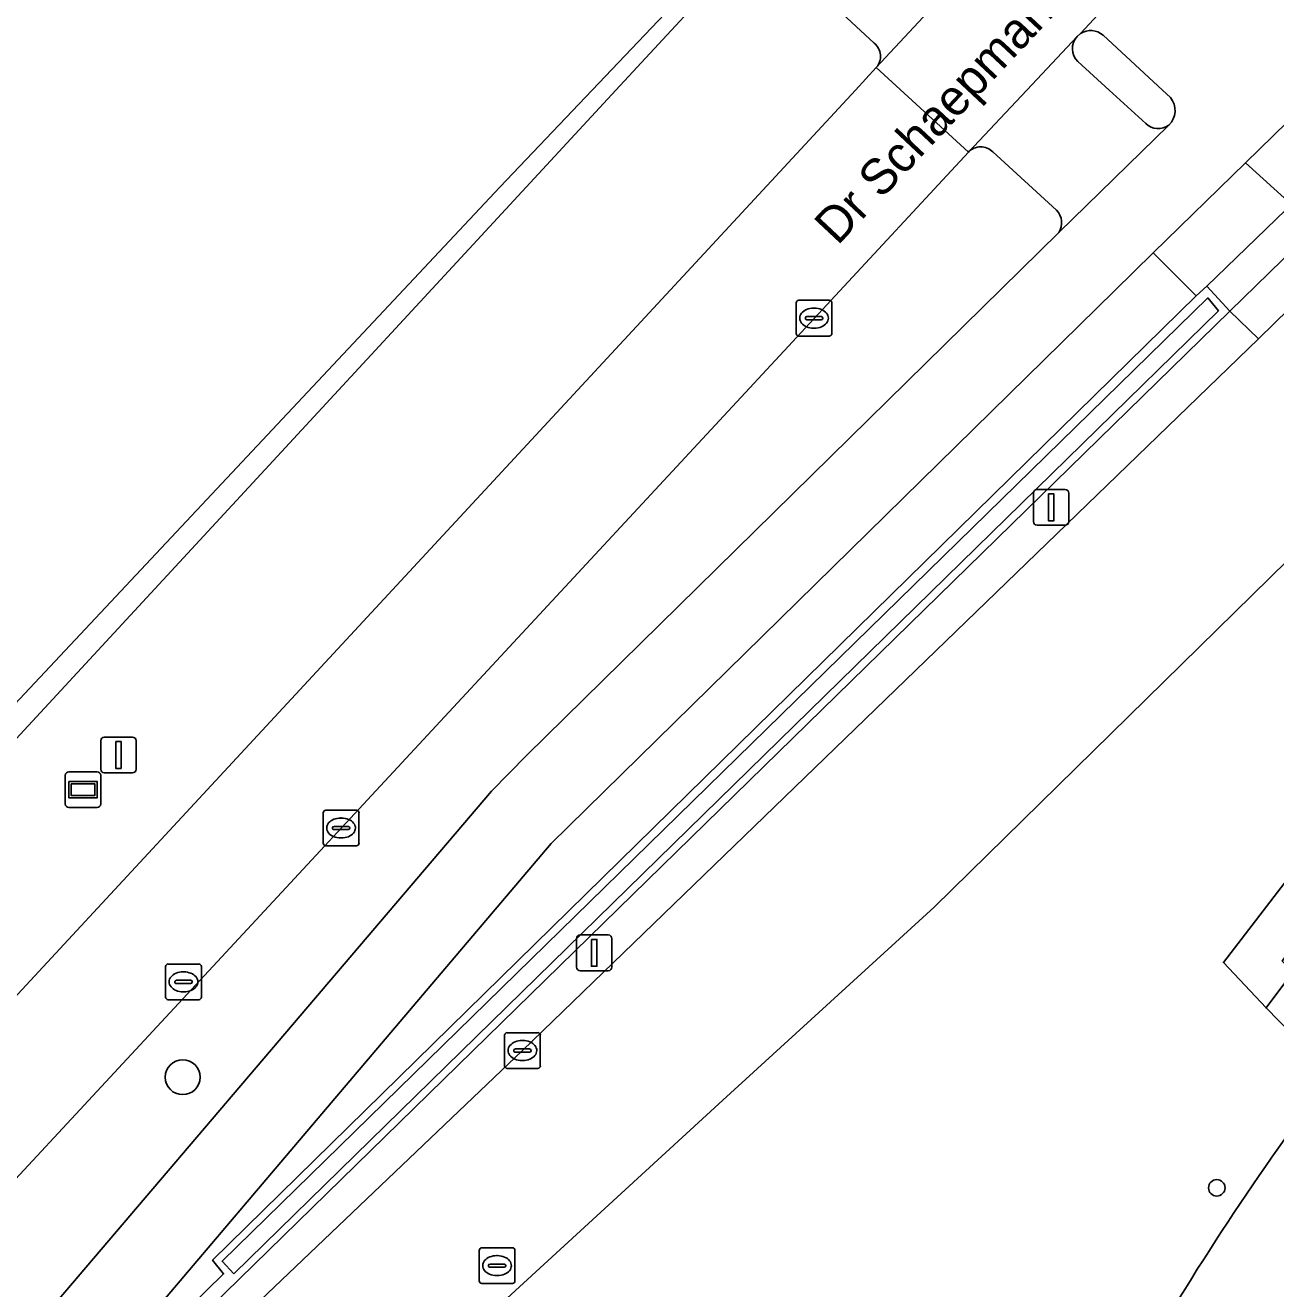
# Model space of a CAD drawing. Extents: x 161402 to 161933, y 381647 to 382315.
# Drawn here: x 161714.34 to 161749.33, y 382216.45 to 382251.82 of the extents above; entities that cross this region are included whole.
import ezdxf

# ---------------------------------------------------------------- set-up
doc = ezdxf.new("R2010")
doc.units = 0
for name, color, linetype in [('IMGEO_Berm_groen', 7, 'Continuous'), ('IMGEO_Boom', 7, 'Continuous'), ('IMGEO_Fietspad_open', 7, 'Continuous'), ('IMGEO_Groenvoorziening', 7, 'Continuous'), ('IMGEO_Kolk', 7, 'Continuous'), ('IMGEO_Lichtmast', 7, 'Continuous'), ('IMGEO_Muur', 7, 'Continuous'), ('IMGEO_Openbare_ruimte_label', 7, 'Continuous'), ('IMGEO_Pand', 7, 'Continuous'), ('IMGEO_Rijbaan_lokaal_gesloten', 7, 'Continuous'), ('IMGEO_Rijbaan_lokaal_open', 7, 'Continuous'), ('IMGEO_Rioolput', 7, 'Continuous'), ('IMGEO_Verkeerseiland_open', 7, 'Continuous'), ('IMGEO_Voetpad_gesloten', 7, 'Continuous'), ('IMGEO_Voetpad_open', 7, 'Continuous'), ('IMGEO_Wegwijzer', 7, 'Continuous')]:
    doc.layers.add(name, color=color, linetype=linetype)

msp = doc.modelspace()

# ---------------------------------------------------------------- linework, layer by layer
at = {"layer": 'IMGEO_Berm_groen'}
for points in [[(161765.113, 382264.207), (161748.486, 382247.967), (161749.768, 382246.799), (161766.553, 382263.178), (161766.895, 382262.953), (161769.85, 382265.834), (161770.184, 382265.542), (161755.779, 382251.492), (161750.251, 382245.958), (161751.001, 382245.149), (161766.659, 382260.549)], [(161734.565, 382254.001), (161730.864, 382250), (161697.412, 382213.802)], [(161738.093, 382251.314), (161735.183, 382254.02)], [(161737.568, 382250), (161738.153, 382250.632)], [(161701.048, 382210.574), (161737.568, 382250)], [(161740.731, 382248.263), (161709.017, 382214.078)], [(161743.193, 382246.637), (161741.415, 382248.269)], [(161727.383, 382230.373), (161728.369, 382231.371), (161743.258, 382246.014)], [(161747.1, 382244.24), (161745.906, 382245.446), (161744.819, 382244.379), (161729.058, 382228.913), (161711.467, 382208.182)], [(161711.914, 382207.765), (161713.169, 382208.748), (161728.253, 382223.117), (161748.845, 382243.038), (161748.046, 382243.815), (161715.85, 382212.342), (161715.57, 382212.632), (161719.892, 382216.863), (161719.584, 382217.248), (161747.1, 382244.24)], [(161709.873, 382209.811), (161727.383, 382230.373)]]:
    msp.add_lwpolyline(points, dxfattribs=at)
for centre, radius, start, end in [((161737.801, 382250.945), 0.471, 318.3858, 51.6697), ((161741.076, 382247.935), 0.476, 44.5516, 136.4535), ((161742.855, 382246.287), 0.487, 325.9277, 45.985)]:
    msp.add_arc(centre, radius, start, end, dxfattribs=at)
at = {"layer": 'IMGEO_Boom'}
msp.add_circle((161718.747, 382222.371), 0.489, dxfattribs=at)
at = {"layer": 'IMGEO_Fietspad_open'}
for points in [[(161689.262, 382184.152), (161697.545, 382192.886), (161698.197, 382193.597), (161711.467, 382208.182), (161729.058, 382228.913), (161744.819, 382244.379), (161745.906, 382245.446), (161748.486, 382247.967), (161765.113, 382264.207)], [(161746.097, 382253.988), (161743.866, 382251.581)], [(161744.502, 382251.534), (161746.159, 382250), (161746.382, 382249.794)], [(161746.337, 382249.017), (161743.258, 382246.014), (161728.369, 382231.371), (161727.383, 382230.373), (161709.873, 382209.811), (161695.051, 382193.536), (161687.761, 382185.921)]]:
    msp.add_lwpolyline(points, dxfattribs=at)
for centre, radius, start, end in [((161744.154, 382251.15), 0.518, 47.7745, 123.7726), ((161745.956, 382249.429), 0.561, 312.7967, 40.5741)]:
    msp.add_arc(centre, radius, start, end, dxfattribs=at)
at = {"layer": 'IMGEO_Groenvoorziening'}
msp.add_lwpolyline([(161720.173, 382216.864), (161747.726, 382243.82), (161747.429, 382244.182), (161719.85, 382217.217)], close=True, dxfattribs=at)
at = {"layer": 'IMGEO_Kolk'}
for p, q in [((161735.911, 382243.191), (161735.911, 382244.043)), ((161735.986, 382244.117), (161736.838, 382244.117)), ((161736.912, 382244.043), (161736.912, 382243.191)), ((161736.399, 382243.897), (161736.424, 382243.897)), ((161736.17, 382243.611), (161736.17, 382243.623)), ((161736.608, 382243.574), (161736.21, 382243.574)), ((161736.213, 382243.66), (161736.611, 382243.66)), ((161736.422, 382243.337), (161736.397, 382243.337)), ((161736.654, 382243.623), (161736.654, 382243.611)), ((161736.838, 382243.117), (161735.986, 382243.117)), ((161722.678, 382228.92), (161722.678, 382229.772)), ((161722.753, 382229.846), (161723.605, 382229.846)), ((161723.166, 382229.626), (161723.191, 382229.626)), ((161723.679, 382229.772), (161723.679, 382228.92)), ((161722.937, 382229.34), (161722.937, 382229.352)), ((161723.375, 382229.303), (161722.977, 382229.303)), ((161722.98, 382229.389), (161723.378, 382229.389)), ((161723.421, 382229.352), (161723.421, 382229.34)), ((161723.605, 382228.846), (161722.753, 382228.846)), ((161723.189, 382229.066), (161723.164, 382229.066)), ((161727.752, 382222.691), (161727.752, 382223.543)), ((161727.827, 382223.617), (161728.679, 382223.617)), ((161728.753, 382223.543), (161728.753, 382222.691)), ((161728.24, 382223.397), (161728.265, 382223.397)), ((161728.011, 382223.111), (161728.011, 382223.123)), ((161728.449, 382223.074), (161728.051, 382223.074)), ((161728.054, 382223.16), (161728.452, 382223.16)), ((161728.263, 382222.837), (161728.238, 382222.837)), ((161728.495, 382223.123), (161728.495, 382223.111)), ((161728.679, 382222.617), (161727.827, 382222.617))]:
    msp.add_line(p, q, dxfattribs=at)
for points in [[(161735.911, 382243.191), (161735.911, 382244.043)], [(161735.986, 382244.117), (161736.838, 382244.117)], [(161736.912, 382244.043), (161736.912, 382243.191)], [(161736.838, 382243.117), (161735.986, 382243.117)], [(161722.678, 382228.92), (161722.678, 382229.772)], [(161722.753, 382229.846), (161723.605, 382229.846)], [(161723.679, 382229.772), (161723.679, 382228.92)], [(161723.605, 382228.846), (161722.753, 382228.846)], [(161727.752, 382222.691), (161727.752, 382223.543)], [(161727.827, 382223.617), (161728.679, 382223.617)], [(161728.753, 382223.543), (161728.753, 382222.691)], [(161728.679, 382222.617), (161727.827, 382222.617)]]:
    msp.add_lwpolyline(points, dxfattribs=at)
for centre, radius, start, end in [((161735.988, 382244.041), 0.0765, 91.552, 178.448), ((161735.988, 382244.041), 0.0765, 91.552, 178.448), ((161736.836, 382244.041), 0.0765, 1.552, 88.448), ((161736.836, 382244.041), 0.0765, 1.552, 88.448), ((161736.21, 382243.62), 0.0403, 85.8775, 175.7526), ((161736.207, 382243.61), 0.0366, 178.938, 274.7102), ((161736.611, 382243.617), 0.043, 264.8664, 352.4533), ((161736.615, 382243.622), 0.0386, 1.7309, 96.639), ((161735.988, 382243.193), 0.0765, 181.552, 268.448), ((161735.988, 382243.193), 0.0765, 181.552, 268.448), ((161736.836, 382243.193), 0.0765, 271.552, 358.448), ((161736.836, 382243.193), 0.0765, 271.552, 358.448), ((161722.755, 382229.77), 0.0765, 91.552, 178.448), ((161722.755, 382229.77), 0.0765, 91.552, 178.448), ((161723.603, 382229.77), 0.0765, 1.552, 88.448), ((161723.603, 382229.77), 0.0765, 1.552, 88.448), ((161722.977, 382229.349), 0.0403, 85.8775, 175.7526), ((161722.974, 382229.339), 0.0366, 178.938, 274.7102), ((161723.378, 382229.346), 0.043, 264.8664, 352.4533), ((161723.382, 382229.351), 0.0386, 1.7309, 96.639), ((161722.755, 382228.922), 0.0765, 181.552, 268.448), ((161722.755, 382228.922), 0.0765, 181.552, 268.448), ((161723.603, 382228.922), 0.0765, 271.552, 358.448), ((161723.603, 382228.922), 0.0765, 271.552, 358.448), ((161727.829, 382223.541), 0.0765, 91.552, 178.448), ((161727.829, 382223.541), 0.0765, 91.552, 178.448), ((161728.677, 382223.541), 0.0765, 1.552, 88.448), ((161728.677, 382223.541), 0.0765, 1.552, 88.448), ((161728.051, 382223.12), 0.0403, 85.8775, 175.7526), ((161728.048, 382223.11), 0.0366, 178.938, 274.7102), ((161728.452, 382223.117), 0.043, 264.8664, 352.4533), ((161728.456, 382223.122), 0.0386, 1.7309, 96.639), ((161727.829, 382222.693), 0.0765, 181.552, 268.448), ((161727.829, 382222.693), 0.0765, 181.552, 268.448), ((161728.677, 382222.693), 0.0765, 271.552, 358.448), ((161728.677, 382222.693), 0.0765, 271.552, 358.448)]:
    msp.add_arc(centre, radius, start, end, dxfattribs=at)
for centre, major_axis, ratio, start_param, end_param in [((161736.398, 382243.617), (-0.387, 0.002), 0.722429, 4.712389, 7.853982), ((161736.423, 382243.617), (-0.39, 0.002), 0.717154, 1.570796, 4.712389), ((161723.165, 382229.346), (-0.387, 0.002), 0.722429, 4.712389, 7.853982), ((161723.19, 382229.346), (-0.39, 0.002), 0.717154, 1.570796, 4.712389), ((161728.239, 382223.117), (-0.387, 0.002), 0.722429, 4.712389, 7.853982), ((161728.264, 382223.117), (-0.39, 0.002), 0.717154, 1.570796, 4.712389)]:
    msp.add_ellipse(centre, major_axis=major_axis, ratio=ratio, start_param=start_param, end_param=end_param, dxfattribs=at)
at = {"layer": 'IMGEO_Lichtmast'}
for p, q in [((161742.652, 382238.821), (161743.442, 382238.821)), ((161743.442, 382238.821), (161742.652, 382238.821)), ((161742.552, 382237.921), (161742.552, 382238.721)), ((161742.552, 382238.721), (161742.552, 382237.921)), ((161743.542, 382238.721), (161743.542, 382237.921)), ((161743.542, 382237.921), (161743.542, 382238.721)), ((161743.442, 382237.821), (161742.652, 382237.821)), ((161742.652, 382237.821), (161743.442, 382237.821)), ((161716.453, 382230.989), (161716.453, 382231.789)), ((161716.453, 382231.789), (161716.453, 382230.989)), ((161716.553, 382231.889), (161717.343, 382231.889)), ((161717.343, 382231.889), (161716.553, 382231.889)), ((161717.443, 382231.789), (161717.443, 382230.989)), ((161717.443, 382230.989), (161717.443, 382231.789)), ((161717.343, 382230.889), (161716.553, 382230.889)), ((161716.553, 382230.889), (161717.343, 382230.889)), ((161729.765, 382225.452), (161729.765, 382226.252)), ((161729.765, 382226.252), (161729.765, 382225.452)), ((161729.865, 382226.352), (161730.655, 382226.352)), ((161730.655, 382226.352), (161729.865, 382226.352)), ((161730.755, 382226.252), (161730.755, 382225.452)), ((161730.755, 382225.452), (161730.755, 382226.252)), ((161730.655, 382225.352), (161729.865, 382225.352)), ((161729.865, 382225.352), (161730.655, 382225.352))]:
    msp.add_line(p, q, dxfattribs=at)
for points in [[(161742.972, 382238.696), (161743.122, 382238.696), (161743.122, 382237.946), (161742.972, 382237.946), (161742.972, 382238.696)], [(161716.873, 382231.764), (161717.023, 382231.764), (161717.023, 382231.014), (161716.873, 382231.014), (161716.873, 382231.764)], [(161730.185, 382226.227), (161730.335, 382226.227), (161730.335, 382225.477), (161730.185, 382225.477), (161730.185, 382226.227)]]:
    msp.add_lwpolyline(points, dxfattribs=at)
for centre, start, end in [((161742.652, 382238.721), 90, 180), ((161742.652, 382238.721), 90, 180), ((161743.442, 382238.721), 0, 90), ((161743.442, 382238.721), 360, 90), ((161742.652, 382237.921), 180, 270), ((161742.652, 382237.921), 180, 270), ((161743.442, 382237.921), 270, 0), ((161743.442, 382237.921), 270, 0), ((161716.553, 382231.789), 90, 180), ((161716.553, 382231.789), 90, 180), ((161717.343, 382231.789), 0, 90), ((161717.343, 382231.789), 360, 90), ((161716.553, 382230.989), 180, 270), ((161716.553, 382230.989), 180, 270), ((161717.343, 382230.989), 270, 0), ((161717.343, 382230.989), 270, 0), ((161729.865, 382226.252), 90, 180), ((161729.865, 382226.252), 90, 180), ((161730.655, 382226.252), 0, 90), ((161730.655, 382226.252), 360, 90), ((161729.865, 382225.452), 180, 270), ((161729.865, 382225.452), 180, 270), ((161730.655, 382225.452), 270, 0), ((161730.655, 382225.452), 270, 0)]:
    msp.add_arc(centre, 0.1, start, end, dxfattribs=at)
at = {"layer": 'IMGEO_Muur'}
for points in [[(161747.399, 382244.517), (161747.1, 382244.24), (161719.584, 382217.248), (161719.892, 382216.863), (161715.57, 382212.632), (161715.85, 382212.342), (161748.046, 382243.815)], [(161720.173, 382216.864), (161719.85, 382217.217), (161747.429, 382244.182), (161747.726, 382243.82)]]:
    msp.add_lwpolyline(points, close=True, dxfattribs=at)
at = {"layer": 'IMGEO_Pand'}
for centre, radius, start, end in [((161816.968, 382172.845), 82.616, 143.12172, 150.09585), ((161747.682, 382219.274), 0.23, 90, 270), ((161747.682, 382219.274), 0.23, 270, 90)]:
    msp.add_arc(centre, radius, start, end, dxfattribs=at)
at = {"layer": 'IMGEO_Rijbaan_lokaal_gesloten'}
for points in [[(161747.864, 382261.109), (161743.521, 382256.439), (161743.425, 382256.334), (161741.178, 382253.892), (161738.153, 382250.632), (161740.731, 382248.263), (161742.363, 382250), (161743.776, 382251.504), (161743.866, 382251.581), (161746.097, 382253.988), (161749.055, 382257.09)], [(161697.412, 382213.802), (161730.864, 382250), (161734.565, 382254.001), (161734.265, 382254.268), (161727.62, 382247.284), (161706.254, 382224.51), (161675.772, 382191.906)], [(161709.017, 382214.078), (161740.731, 382248.263), (161738.153, 382250.632), (161737.568, 382250), (161701.048, 382210.574), (161693.624, 382202.616), (161684.055, 382192.367), (161681.452, 382189.793)]]:
    msp.add_lwpolyline(points, dxfattribs=at)
at = {"layer": 'IMGEO_Rijbaan_lokaal_open'}
for points in [[(161766.659, 382260.549), (161751.001, 382245.149), (161748.845, 382243.038), (161728.253, 382223.117), (161713.169, 382208.748), (161711.914, 382207.765)], [(161710.972, 382200.713), (161733.859, 382221.725), (161739.772, 382227.133), (161755.602, 382242.666)]]:
    msp.add_lwpolyline(points, dxfattribs=at)
at = {"layer": 'IMGEO_Rioolput'}
for p, q in [((161718.268, 382224.613), (161718.268, 382225.465)), ((161718.343, 382225.539), (161719.195, 382225.539)), ((161718.756, 382225.319), (161718.781, 382225.319)), ((161719.269, 382225.465), (161719.269, 382224.613)), ((161718.527, 382225.033), (161718.527, 382225.045)), ((161718.965, 382224.996), (161718.567, 382224.996)), ((161718.57, 382225.082), (161718.968, 382225.082)), ((161719.011, 382225.045), (161719.011, 382225.033)), ((161718.779, 382224.759), (161718.754, 382224.759)), ((161719.195, 382224.539), (161718.343, 382224.539)), ((161727.043, 382216.67), (161727.043, 382217.522)), ((161727.118, 382217.596), (161727.97, 382217.596)), ((161728.044, 382217.522), (161728.044, 382216.67)), ((161727.531, 382217.376), (161727.556, 382217.376)), ((161727.302, 382217.09), (161727.302, 382217.102)), ((161727.74, 382217.053), (161727.342, 382217.053)), ((161727.345, 382217.139), (161727.743, 382217.139)), ((161727.554, 382216.816), (161727.529, 382216.816)), ((161727.786, 382217.102), (161727.786, 382217.09)), ((161727.97, 382216.596), (161727.118, 382216.596))]:
    msp.add_line(p, q, dxfattribs=at)
for points in [[(161718.268, 382224.613), (161718.268, 382225.465)], [(161718.343, 382225.539), (161719.195, 382225.539)], [(161719.269, 382225.465), (161719.269, 382224.613)], [(161719.195, 382224.539), (161718.343, 382224.539)], [(161727.043, 382216.67), (161727.043, 382217.522)], [(161727.118, 382217.596), (161727.97, 382217.596)], [(161728.044, 382217.522), (161728.044, 382216.67)], [(161727.97, 382216.596), (161727.118, 382216.596)]]:
    msp.add_lwpolyline(points, dxfattribs=at)
for centre, radius, start, end in [((161718.345, 382225.463), 0.0765, 91.552, 178.448), ((161718.345, 382225.463), 0.0765, 91.552, 178.448), ((161719.193, 382225.463), 0.0765, 1.552, 88.448), ((161719.193, 382225.463), 0.0765, 1.552, 88.448), ((161718.567, 382225.042), 0.0403, 85.8775, 175.7526), ((161718.564, 382225.032), 0.0366, 178.938, 274.7102), ((161718.968, 382225.039), 0.043, 264.8664, 352.4533), ((161718.972, 382225.044), 0.0386, 1.7309, 96.639), ((161718.345, 382224.615), 0.0765, 181.552, 268.448), ((161718.345, 382224.615), 0.0765, 181.552, 268.448), ((161719.193, 382224.615), 0.0765, 271.552, 358.448), ((161719.193, 382224.615), 0.0765, 271.552, 358.448), ((161727.12, 382217.52), 0.0765, 91.552, 178.448), ((161727.12, 382217.52), 0.0765, 91.552, 178.448), ((161727.968, 382217.52), 0.0765, 1.552, 88.448), ((161727.968, 382217.52), 0.0765, 1.552, 88.448), ((161727.342, 382217.099), 0.0403, 85.8775, 175.7526), ((161727.339, 382217.089), 0.0366, 178.938, 274.7102), ((161727.743, 382217.096), 0.043, 264.8664, 352.4533), ((161727.747, 382217.101), 0.0386, 1.7309, 96.639), ((161727.12, 382216.672), 0.0765, 181.552, 268.448), ((161727.12, 382216.672), 0.0765, 181.552, 268.448), ((161727.968, 382216.672), 0.0765, 271.552, 358.448), ((161727.968, 382216.672), 0.0765, 271.552, 358.448)]:
    msp.add_arc(centre, radius, start, end, dxfattribs=at)
for centre, major_axis, ratio, start_param, end_param in [((161718.755, 382225.039), (-0.387, 0.002), 0.722429, 4.712389, 7.853982), ((161718.78, 382225.039), (-0.39, 0.002), 0.717154, 1.570796, 4.712389), ((161727.53, 382217.096), (-0.387, 0.002), 0.722429, 4.712389, 7.853982), ((161727.555, 382217.096), (-0.39, 0.002), 0.717154, 1.570796, 4.712389)]:
    msp.add_ellipse(centre, major_axis=major_axis, ratio=ratio, start_param=start_param, end_param=end_param, dxfattribs=at)
at = {"layer": 'IMGEO_Verkeerseiland_open'}
for points in [[(161743.866, 382251.581), (161743.776, 382251.504)], [(161746.382, 382249.794), (161746.159, 382250), (161744.502, 382251.534)], [(161743.794, 382250.802), (161744.671, 382250), (161745.696, 382249.062)]]:
    msp.add_lwpolyline(points, dxfattribs=at)
for centre, radius, start, end in [((161744.144, 382251.162), 0.502, 137.1337, 225.8039), ((161744.154, 382251.15), 0.518, 47.7745, 123.7726), ((161745.956, 382249.429), 0.561, 312.7967, 40.5741), ((161746.043, 382249.422), 0.5, 226.0253, 305.9432)]:
    msp.add_arc(centre, radius, start, end, dxfattribs=at)
at = {"layer": 'IMGEO_Voetpad_gesloten'}
for points in [[(161747.399, 382244.517), (161748.046, 382243.815), (161750.251, 382245.958), (161749.616, 382246.65)], [(161750.499, 382224.592), (161749.811, 382225.312), (161749.059, 382224.31), (161749.77, 382223.583), (161750.883, 382222.424), (161751.568, 382223.506)]]:
    msp.add_lwpolyline(points, close=True, dxfattribs=at)
msp.add_lwpolyline([(161749.786, 382228.073), (161747.869, 382225.581), (161749.059, 382224.31), (161749.811, 382225.312), (161749.515, 382225.622), (161750.706, 382227.341)], dxfattribs=at)
at = {"layer": 'IMGEO_Voetpad_open'}
for points in [[(161832.261, 382288.126), (161785.98, 382272.346), (161785.755, 382272.254), (161777.222, 382263.881), (161755.602, 382242.666), (161739.772, 382227.133), (161733.859, 382221.725), (161710.972, 382200.713)], [(161735.183, 382254.02), (161738.093, 382251.314)], [(161738.153, 382250.632), (161741.178, 382253.892)], [(161743.776, 382251.504), (161742.363, 382250), (161740.731, 382248.263)], [(161745.696, 382249.062), (161744.671, 382250), (161743.794, 382250.802)], [(161743.258, 382246.014), (161746.337, 382249.017)], [(161741.415, 382248.269), (161743.193, 382246.637)], [(161750.883, 382222.424), (161749.77, 382223.583), (161749.059, 382224.31), (161747.869, 382225.581), (161749.786, 382228.073)]]:
    msp.add_lwpolyline(points, dxfattribs=at)
for points in [[(161749.616, 382246.65), (161749.768, 382246.799), (161748.486, 382247.967), (161745.906, 382245.446), (161747.1, 382244.24), (161747.399, 382244.517)], [(161751.001, 382245.149), (161750.251, 382245.958), (161748.046, 382243.815), (161748.845, 382243.038)]]:
    msp.add_lwpolyline(points, close=True, dxfattribs=at)
for centre, radius, start, end in [((161744.144, 382251.162), 0.502, 137.1337, 225.8039), ((161737.801, 382250.945), 0.471, 318.3858, 51.6697), ((161746.043, 382249.422), 0.5, 226.0253, 305.9432), ((161741.076, 382247.935), 0.476, 44.5516, 136.4535), ((161742.855, 382246.287), 0.487, 325.9277, 45.985), ((161816.968, 382172.845), 82.616, 143.12172, 150.09585), ((161747.682, 382219.274), 0.23, 90, 270), ((161747.682, 382219.274), 0.23, 270, 90)]:
    msp.add_arc(centre, radius, start, end, dxfattribs=at)
at = {"layer": 'IMGEO_Wegwijzer'}
for p, q in [((161715.462, 382230.019), (161715.462, 382230.819)), ((161715.462, 382230.819), (161715.462, 382230.019)), ((161715.562, 382230.919), (161716.352, 382230.919)), ((161716.352, 382230.919), (161715.562, 382230.919)), ((161716.452, 382230.819), (161716.452, 382230.019)), ((161716.452, 382230.019), (161716.452, 382230.819)), ((161716.352, 382229.919), (161715.562, 382229.919)), ((161715.562, 382229.919), (161716.352, 382229.919))]:
    msp.add_line(p, q, dxfattribs=at)
for points in [[(161715.563, 382230.651), (161716.351, 382230.651), (161716.351, 382230.187), (161715.563, 382230.187), (161715.563, 382230.651)], [(161715.628, 382230.586), (161715.628, 382230.252), (161716.286, 382230.252), (161716.286, 382230.586), (161715.628, 382230.586)]]:
    msp.add_lwpolyline(points, dxfattribs=at)
for centre, start, end in [((161715.562, 382230.819), 90, 180), ((161715.562, 382230.819), 90, 180), ((161716.352, 382230.819), 0, 90), ((161716.352, 382230.819), 360, 90), ((161715.562, 382230.019), 180, 270), ((161715.562, 382230.019), 180, 270), ((161716.352, 382230.019), 270, 0), ((161716.352, 382230.019), 270, 0)]:
    msp.add_arc(centre, 0.1, start, end, dxfattribs=at)

# ---------------------------------------------------------------- texts
at = {"layer": 'IMGEO_Openbare_ruimte_label'}
msp.add_text('Dr Schaepmanlaan', height=1, rotation=46.8241, dxfattribs=at).set_placement((161737.071, 382245.63))

doc.saveas('drawing.dxf')
